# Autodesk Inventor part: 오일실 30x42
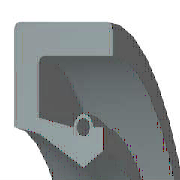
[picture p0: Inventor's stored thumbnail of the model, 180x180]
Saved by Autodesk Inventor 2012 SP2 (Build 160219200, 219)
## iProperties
IsCustomPart: 0
Company: 한국ATC센터
Created: 2009-02
Part Number: 오일실 30x42
Material: 고무
Description: 오일-실
Document SubType Name: Modeling
Standard: KS B 2804
Designer: KYOUNG IL JANG
Standards Organization: KS
Language: ko-KR
Size Designation: S - 30 42 8
Categories: <MemberInstance><Categories><Category DisplayName="샤프트 부품" InternalName="7f7aeb1f-a693-4053-b835-cee3144e0d98" Mnemonic="SHFT"><Category DisplayName="실링" Intern
Density: 0.93 g/cm^3
Author: KYOUNG IL JANG
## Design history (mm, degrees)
revolve "본체" stored, may be unused: angle "d17" = 90 deg
revolve "스프링1" stored, may be unused: angle "d18" = 90 deg
body "Solid1"
sketch "스케치1"
  geometry: L1 (0, 21)-(8, 21); L2 (8, 21)-(8, 19.75); L3 (8, 19.75)-(1.75, 19.75); L4 (0, 21)-(0, 17.1); L5 (0, 17.1)-(1.75, 16.75); L6 (1.75, 16.75)-(4.9, 15); L7 (4.9, 15)-(0, 15); L8 (6.3, 15.875)-(6.3, 17.1); L9 (0, 0)-(9.586, 0) reference; L10 (4.9, 15)-(6.3, 15.875); L11 (0, 18)-(0, -3) reference; L12 (-1.917, 0)-(11.503, 0) reference; L13 (4.2, 17.1)-(1.75, 17.59); L14 (1.75, 17.59)-(1.75, 19.75); L15 (6.3, 17.1)-(5.6, 17.1); C1 r 0.455 at (4.9, 17.1); A1 r 0.7 centre (4.9, 17.1) between (5.6, 17.1) and (4.2, 17.1)
  constraints: 26 end point, 5 horizontal alignment, 4 perpendicular, 2 centre point, 2 collinear, 2 horizontal, 2 parallel, 2 point on circle, 2 point on line, 2 vertical alignment, 1 coincident
  dimensions: "d0" = 42 diameter of L1 L9 (= SD2); "d1" = 31.75 diameter of L8.start L9 (= ABDM); "d2" = 1.25 distance of L1.end L2.end (computed from SD); "d3" = 0.91 diameter of C1 (= SPDI); "d4" = 1.4 diameter of A1 (= SPDA); "d5" = 30 diameter of L6.end L9 (= NND); "d6" = 33.5 diameter of L5.end L9 (= TKDM); "d7" = 34.2 diameter of L4.end L9 (= HLDM); "d8" = 4.9 distance from line of C1.centre L4 (= SPDST); "d9" = 6.3 distance between parallel lines of L8 L4 (= SDI); "d10" = 8 distance between parallel lines of L2 L4 (= SWDT); "d12" = 1.75 distance between parallel lines of L14 L4 (= SD)
fillet "모깎기1" dims "d11" = 0.4 (= RR)
other parameters: "SD2" = 42 [user parameter; used in 1 equation term], "SWDT" = 8 [user parameter; used in 1 equation term], "RR" = 0.4 [user parameter; used in 1 equation term], "SD" = 1.75 [user parameter; used in 2 equation terms], "NND" = 30 [user parameter; used in 1 equation term], "SPDA" = 1.4 [user parameter; used in 1 equation term], "SPDI" = 0.91 [user parameter; used in 1 equation term], "TKDM" = 33.5 [user parameter; used in 1 equation term], "HLDM" = 34.2 [user parameter; used in 1 equation term], "ABDM" = 31.75 [user parameter; used in 1 equation term], "SDI" = 6.3 [user parameter; used in 1 equation term], "SPDST" = 4.9 [user parameter; used in 1 equation term], "d13" = 0, "d14" = 0, "d15" = 0, "LAB" = 0.35 [user parameter]
